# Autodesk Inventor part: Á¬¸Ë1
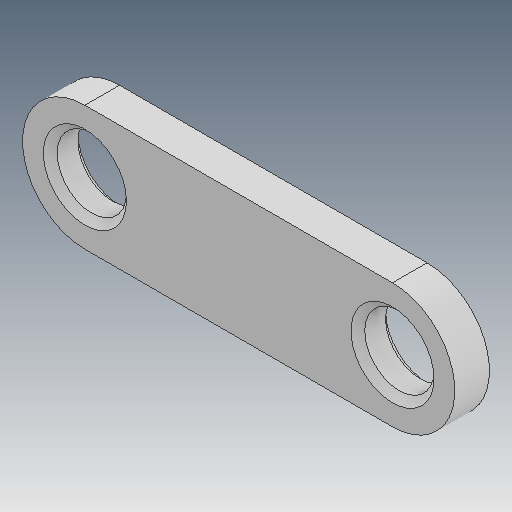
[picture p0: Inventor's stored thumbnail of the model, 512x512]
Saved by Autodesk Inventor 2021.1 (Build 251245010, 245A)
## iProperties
Created: 2015-08
Part Number: Á¬¸Ë1
Material: Ogólny
Document SubType Name: Modeling
Designer: user
Density: 1 g/cm^3
Appearance: Domyślna
Author: user
Revision Number: ÈÎºÎ
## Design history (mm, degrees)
feature "µ¹½Ç1"
node "Bryła1"
